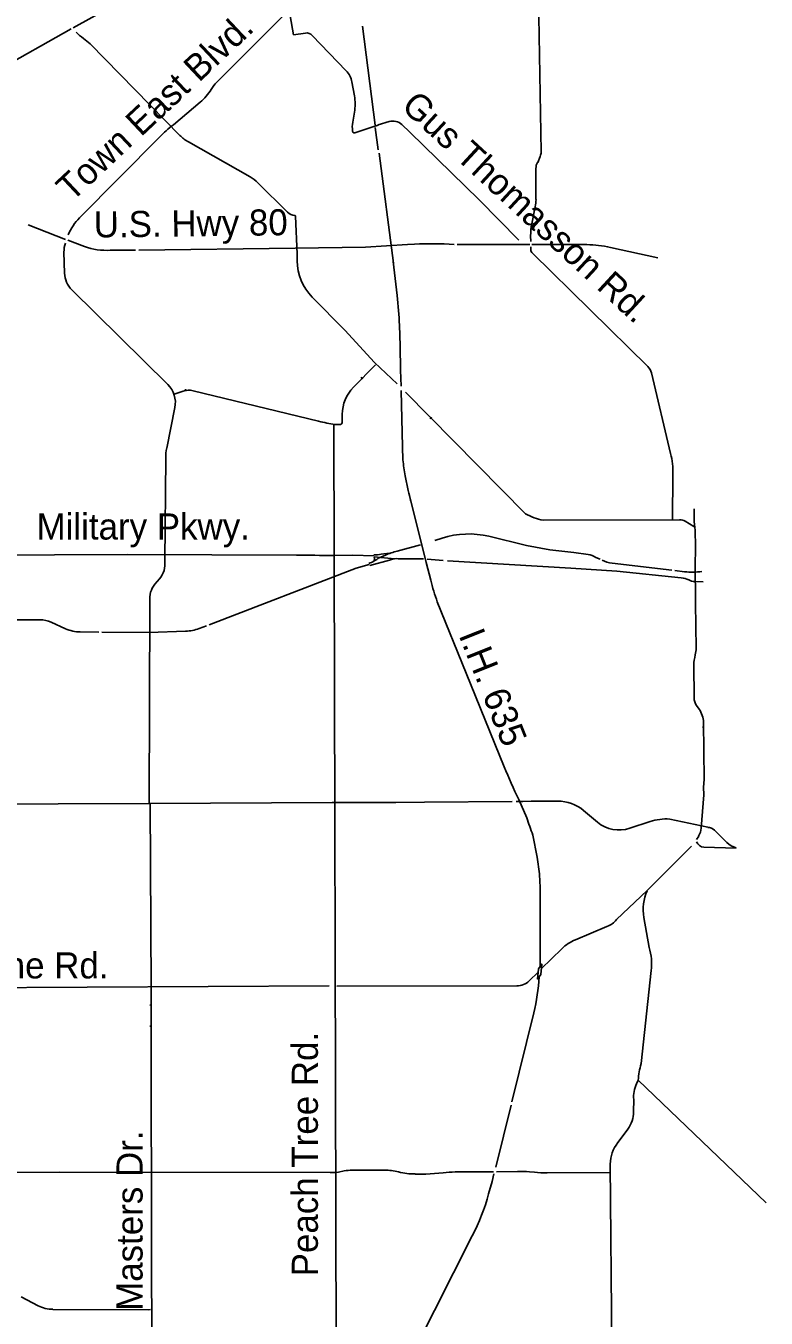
# Model space of a CAD drawing. Extents: x 105094 to 105814, y -291615 to -291123.
# Drawn here: x 105517.8 to 105552.1, y -291508 to -291448 of the extents above; entities that cross this region are included whole.
import ezdxf

# ---------------------------------------------------------------- set-up
doc = ezdxf.new("R2010")
doc.units = 0
doc.layers.add('G_MAP', color=7, linetype='Continuous')

msp = doc.modelspace()

# ---------------------------------------------------------------- linework, layer by layer
at = {"layer": 'G_MAP'}
for p, q in [((105526.465, -291444.508), (105519.999, -291448.096)), ((105530.218, -291448.416), (105529.816, -291446.081)), ((105541.705, -291453.857), (105541.589, -291446.659)), ((105526.657, -291450.614), (105529.889, -291447.382)), ((105519.912, -291448.148), (105513.437, -291451.781)), ((105530.771, -291448.338), (105530.218, -291448.416)), ((105533.418, -291448.019), (105534.006, -291452.608)), ((105532.66, -291450.087), (105531.087, -291448.447)), ((105533.045, -291451.257), (105532.926, -291450.606)), ((105524.65, -291452.595), (105525.896, -291451.545)), ((105532.967, -291452.48), (105533.049, -291452.006)), ((105533.848, -291452.699), (105534.145, -291452.608)), ((105534.145, -291452.605), (105534.654, -291452.449)), ((105520.292, -291456.912), (105524.004, -291453.176)), ((105532.965, -291452.906), (105532.96, -291452.876)), ((105533.848, -291452.699), (105533.067, -291452.969)), ((105534.009, -291452.718), (105534.148, -291453.755)), ((105525.343, -291453.39), (105528.211, -291455.012)), ((105534.19, -291453.906), (105534.858, -291459.023)), ((105541.547, -291454.339), (105541.667, -291454.061)), ((105541.469, -291456.065), (105541.469, -291454.62)), ((105528.566, -291455.281), (105529.948, -291456.653)), ((105541.275, -291457.192), (105541.436, -291456.395)), ((105517.907, -291457.239), (105519.641, -291457.911)), ((105530.319, -291456.842), (105530.386, -291458.595)), ((105519.757, -291457.946), (105520.526, -291458.237)), ((105541.224, -291458.014), (105541.221, -291457.755)), ((105519.602, -291459.472), (105519.572, -291458.503)), ((105521.721, -291458.414), (105522.896, -291458.414)), ((105523.045, -291458.411), (105530.302, -291458.321)), ((105530.302, -291458.321), (105533.554, -291458.266)), ((105530.386, -291458.595), (105530.39, -291458.907)), ((105541.176, -291458.143), (105537.807, -291458.15)), ((105541.227, -291458.374), (105541.224, -291458.256)), ((105546.65, -291463.804), (105541.303, -291458.557)), ((105544.923, -291458.282), (105547.121, -291458.763)), ((105534.849, -291458.941), (105535.028, -291460.518)), ((105524.393, -291464.651), (105519.939, -291460.25)), ((105534.019, -291463.727), (105533.001, -291464.769)), ((105533.363, -291464.312), (105533.428, -291464.396)), ((105547.715, -291467.844), (105546.823, -291464.109)), ((105525.095, -291464.953), (105524.64, -291465.103)), ((105525.209, -291464.86), (105525.231, -291464.954)), ((105531.387, -291466.349), (105525.563, -291464.934)), ((105535.411, -291464.999), (105540.985, -291470.638)), ((105524.338, -291467.591), (105524.717, -291465.715)), ((105532.485, -291466.035), (105532.485, -291466.381)), ((105536.564, -291466.243), (105536.625, -291466.168)), ((105532.097, -291466.509), (105532.215, -291515.51)), ((105532.356, -291466.508), (105532.143, -291466.504)), ((105524.25, -291472.828), (105524.291, -291468.068)), ((105547.809, -291470.951), (105547.822, -291468.807)), ((105535.405, -291468.878), (105535.547, -291469.559)), ((105535.605, -291469.802), (105536.38, -291472.908)), ((105541.809, -291470.942), (105548.131, -291470.918)), ((105548.397, -291470.992), (105548.784, -291471.226)), ((105536.774, -291471.885), (105537.115, -291471.774)), ((105535.033, -291472.379), (105536.105, -291472.085)), ((105532.072, -291472.585), (105532.976, -291472.556)), ((105532.976, -291472.556), (105533.945, -291472.592)), ((105533.131, -291473.16), (105533.729, -291472.992)), ((105533.761, -291473.047), (105534.678, -291472.802)), ((105533.958, -291472.643), (105534.901, -291472.731)), ((105534.194, -291472.679), (105534.481, -291472.563)), ((105534.287, -291472.521), (105534.681, -291472.463)), ((105535.079, -291472.731), (105536.244, -291472.737)), ((105536.38, -291472.908), (105536.587, -291473.722)), ((105536.425, -291472.753), (105537.158, -291472.815)), ((105544.25, -291472.666), (105544.447, -291472.744)), ((105545.005, -291472.932), (105547.764, -291473.257)), ((105533.131, -291473.16), (105526.31, -291475.799)), ((105547.903, -291473.276), (105548.362, -291473.33)), ((105523.785, -291473.909), (105524.004, -291473.667)), ((105548.83, -291473.788), (105549.221, -291473.793)), ((105523.523, -291484.082), (105523.559, -291474.707)), ((105536.89, -291474.726), (105538.224, -291478.033)), ((105518.452, -291475.563), (105513.069, -291475.56)), ((105519.646, -291475.975), (105518.981, -291475.677)), ((105526.181, -291475.844), (105525.836, -291475.969)), ((105521.195, -291476.131), (105520.329, -291476.125)), ((105548.792, -291477.672), (105548.805, -291479.173)), ((105538.224, -291478.033), (105539.996, -291482.379)), ((105548.92, -291479.541), (105549.035, -291479.708)), ((105549.263, -291480.543), (105549.201, -291480.543)), ((105549.208, -291480.769), (105549.263, -291480.769)), ((105549.24, -291480.318), (105549.266, -291482.978)), ((105534.969, -291484.043), (105536.299, -291484.021)), ((105536.299, -291484.021), (105540.362, -291483.995)), ((105540.543, -291483.995), (105540.856, -291483.989)), ((105541.043, -291484.744), (105540.672, -291483.901)), ((105543.673, -291484.407), (105544.322, -291484.949)), ((105545.82, -291485.233), (105546.76, -291484.922)), ((105547.674, -291484.806), (105549.437, -291485.19)), ((105541.521, -291486.572), (105541.324, -291485.549)), ((105548.92, -291485.759), (105549.016, -291485.598)), ((105549.75, -291485.329), (105550.323, -291485.888)), ((105541.657, -291491.646), (105541.668, -291488.627)), ((105543.303, -291490.403), (105544.763, -291489.792)), ((105546.473, -291489.37), (105546.714, -291490.764)), ((105541.715, -291491.762), (105542.673, -291490.821)), ((105541.154, -291492.317), (105541.569, -291491.917)), ((105546.808, -291491.837), (105546.344, -291496.153)), ((105532.223, -291492.557), (105540.584, -291492.547)), ((105523.645, -291493.429), (105523.558, -291493.436)), ((105540.355, -291497.921), (105541.365, -291493.8)), ((105523.558, -291494.421), (105523.645, -291494.417)), ((105546.21, -291496.927), (105546.135, -291497.088)), ((105539.599, -291500.957), (105540.313, -291498.083)), ((105546.003, -291497.811), (105546, -291498.388)), ((105532.568, -291501.133), (105532.31, -291501.187)), ((105534.439, -291501.096), (105532.934, -291501.096)), ((105537.722, -291501.177), (105539.499, -291501.17)), ((105539.644, -291501.167), (105540.613, -291501.157)), ((105541.165, -291501.17), (105541.399, -291501.195)), ((105541.991, -291501.225), (105544.927, -291501.203)), ((105534.008, -291513.065), (105538.513, -291504.143)), ((105517.584, -291506.98), (105518.368, -291507.384)), ((105519.056, -291507.553), (105523.48, -291507.572)), ((105523.483, -291507.572), (105523.583, -291507.565))]:
    msp.add_line(p, q, dxfattribs=at)
for points in [[(105520.474, -291448.587), (105520.791, -291448.845), (105524.946, -291453.086)], [(105535.248, -291452.587), (105535.618, -291452.934), (105538.831, -291456.083), (105540.675, -291457.946)], [(105535.837, -291458.13), (105535.501, -291458.143), (105533.554, -291458.266)], [(105541.282, -291458.15), (105542.635, -291458.146), (105543.823, -291458.157)], [(105531.087, -291460.587), (105532.605, -291462.128), (105533.974, -291463.617), (105535.023, -291464.618)], [(105535.131, -291461.899), (105535.166, -291462.845), (105535.188, -291463.976), (105535.208, -291464.718)], [(105535.217, -291464.925), (105535.282, -291467.535), (105535.295, -291468.138)], [(105548.803, -291470.414), (105548.807, -291470.876)], [(105539.286, -291471.688), (105541.034, -291472.107), (105542.109, -291472.311), (105543.227, -291472.443), (105543.882, -291472.527)], [(105548.862, -291472.017), (105548.862, -291472.363), (105548.856, -291472.915), (105548.862, -291474.794), (105548.894, -291476.887)], [(105512.391, -291472.579), (105522.503, -291472.527), (105530.354, -291472.56)], [(105537.365, -291472.831), (105543.085, -291473.167), (105545.226, -291473.302), (105548.208, -291473.612)], [(105525.215, -291476.09), (105523.523, -291476.151), (105521.324, -291476.135)], [(105549.133, -291485.231), (105549.25, -291483.688), (105549.247, -291483.33), (105549.266, -291482.978)], [(105519.296, -291484.105), (105514.984, -291484.128), (105508.486, -291484.138)], [(105534.969, -291484.043), (105532.017, -291484.043), (105523.559, -291484.079), (105519.296, -291484.105)], [(105523.568, -291484.076), (105523.613, -291492.654), (105523.619, -291498.845), (105523.629, -291501.2), (105523.644, -291512.878)], [(105540.856, -291483.989), (105541.25, -291483.972), (105542.475, -291483.972)], [(105545.203, -291489.466), (105546.624, -291488.113), (105548.681, -291486.065)], [(105549.259, -291486.116), (105550.752, -291486.159)], [(105531.874, -291492.55), (105515.016, -291492.635), (105506.487, -291492.69), (105492.846, -291492.719)], [(105552.147, -291502.617), (105546.21, -291496.927)], [(105545.731, -291499.19), (105545.422, -291499.617), (105545.263, -291499.819)], [(105531.916, -291501.203), (105519.379, -291501.187), (105515.038, -291501.209), (105506.545, -291501.232), (105501.303, -291501.268)], [(105544.911, -291500.815), (105544.985, -291509.351), (105544.957, -291510.894)], [(105535.868, -291501.274), (105536.356, -291501.274), (105537.167, -291501.212)], [(105539.273, -291502.198), (105539.431, -291501.629), (105539.518, -291501.267)]]:
    msp.add_lwpolyline(points, dxfattribs=at)
msp.add_lwpolyline([(105541.578, -291491.754), (105541.539, -291492.232), (105541.696, -291492.016), (105541.735, -291491.538)], close=True, dxfattribs=at)
for centre, radius, start, end in [((105523.895, -291444.211), 5.555, 227.34965, 231.98343), ((105530.822, -291448.701), 0.367, 43.82932, 98.08015), ((105531.931, -291450.787), 1.011, 10.32319, 43.84286), ((105527.726, -291451.681), 1.51, 135.03617, 151.16716), ((105524.346, -291449.705), 2.406, 310.10155, 328.7471), ((105530.94, -291451.643), 2.14, 350.21938, 10.38066), ((105527.303, -291456.192), 4.47, 126.40722, 137.56399), ((105534.267, -291452.701), 1.318, 170.35143, 187.62976), ((105534.832, -291453.029), 0.607, 46.7474, 107.06266), ((105526.22, -291451.838), 1.783, 224.42286, 240.52914), ((105533.041, -291452.896), 0.0774, 186.97324, 289.24024), ((105541.911, -291454.591), 0.443, 145.35516, 183.80648), ((105541.238, -291453.876), 0.467, 336.66831, 2.43907), ((105527.389, -291456.466), 1.67, 45.19952, 60.52826), ((105539.814, -291456.065), 1.656, 348.51587, 0.00435), ((105530.313, -291456.281), 0.521, 225.50225, 265.99529), ((105530.276, -291456.844), 0.0434, 3.06758, 88.22489), ((105521.978, -291458.586), 2.376, 135.20764, 158.13049), ((105543.974, -291457.736), 2.754, 168.60216, 180.39535), ((105520.639, -291458.476), 1.067, 158.32364, 181.46081), ((105521.532, -291455.576), 2.845, 249.28493, 273.80348), ((105536.603, -291479.394), 21.277, 87.13102, 92.06356), ((105541.48, -291458.376), 0.254, 179.72845, 225.52704), ((105543.775, -291463.523), 5.366, 77.63794, 89.48528), ((105532.819, -291458.883), 2.429, 180.56241, 224.53494), ((105520.737, -291459.442), 1.136, 181.53535, 225.3349), ((105517.082, -291462.558), 18.061, 2.09036, 6.48338), ((105546.208, -291464.255), 0.632, 13.35876, 45.54423), ((105523.571, -291465.483), 1.169, 348.5631, 45.34707), ((105525.362, -291465.762), 0.853, 76.33036, 108.25931), ((105534.297, -291466.035), 1.812, 135.65979, 180.00048), ((105533.601, -291457.476), 9.145, 255.98943, 260.82432), ((105532.358, -291466.381), 0.127, 269.00527, 0), ((105526.705, -291468.064), 2.413, 168.68432, 180.10112), ((105542.237, -291467.481), 6.973, 185.41365, 191.55912), ((105543.913, -291468.755), 3.91, 359.23225, 13.46001), ((105529.598, -291471.115), 6.149, 10.00387, 14.65608), ((105542.119, -291468.832), 2.132, 237.889, 261.64094), ((105548.132, -291471.429), 0.511, 58.83031, 90.20674), ((105552.259, -291470.866), 3.452, 180.17123, 188.95349), ((105538.352, -291475.581), 4.003, 76.50486, 108.00496), ((105548.859, -291471.102), 0.145, 238.74031, 257.72294), ((105535.735, -291471.987), 13.127, 359.86913, 2.547), ((105535.577, -291474.93), 2.608, 102.02689, 114.83996), ((105523.17, -291472.968), 1.089, 320.02559, 7.38803), ((105529.886, -291560.846), 88.288, 88.5814, 89.69655), ((105533.045, -291471.204), 1.869, 290.91368, 307.9082), ((105533.896, -291469.953), 2.597, 271.08424, 278.6647), ((105533.799, -291472.739), 0.182, 323.36324, 24.61877), ((105534.99, -291473.394), 0.669, 82.37625, 117.74502), ((105543.585, -291473.873), 1.378, 61.12614, 77.54593), ((105545.173, -291471.463), 1.478, 244.28398, 263.49849), ((105548.1, -291474.634), 1.028, 63.71722, 83.98865), ((105548.732, -291470.13), 3.221, 263.40804, 277.68412), ((105524.631, -291474.58), 1.08, 141.60041, 186.75615), ((105547.115, -291471.088), 10.852, 194.04792, 199.58954), ((105548.838, -291473.222), 0.567, 240.06495, 269.13937), ((105518.452, -291476.855), 1.292, 65.80187, 89.97171), ((105520.342, -291474.425), 1.7, 245.80967, 269.53812), ((105525.142, -291474.055), 2.036, 272.06884, 289.93667), ((105550.731, -291477.693), 1.938, 164.83363, 179.37717), ((105547.791, -291476.913), 1.103, 345.64916, 1.34559), ((105549.455, -291479.171), 0.651, 180.10698, 214.61714), ((105548.08, -291480.367), 1.161, 2.4166, 34.62684), ((105562.541, -291473.279), 24.312, 201.98286, 205.90794), ((105542.475, -291485.842), 1.869, 50.13969, 89.99489), ((105555.884, -291480.012), 15.577, 197.68622, 200.81986), ((105545.327, -291483.745), 1.568, 230.13872, 288.33733), ((105547.527, -291487.307), 2.506, 86.65439, 107.8424), ((105548.292, -291485.166), 0.843, 329.15507, 355.59272), ((105549.39, -291485.72), 0.532, 47.29803, 84.87942), ((105549.269, -291485.753), 0.363, 196.34033, 268.38506), ((105551.099, -291485.092), 1.111, 225.76598, 251.74313), ((105533.944, -291487.987), 7.708, 3.89276, 10.57936), ((105524.43, -291488.547), 17.238, 359.73536, 3.60417), ((105548.599, -291489.003), 2.157, 156.08771, 189.7886), ((105544.435, -291488.892), 0.959, 290.01851, 323.17591), ((105544.074, -291492.248), 2, 112.699, 134.47801), ((105544.453, -291491.502), 2.379, 351.9116, 18.0637), ((105532.277, -291491.57), 9.357, 346.21568, 356.60517), ((105540.583, -291491.724), 0.824, 270.06308, 313.90486), ((105550.085, -291497.202), 3.885, 164.33712, 175.94081), ((105547.281, -291497.672), 1.285, 152.99951, 186.24918), ((105544.586, -291498.36), 1.414, 324.08479, 358.88243), ((105546.565, -291500.839), 1.654, 141.90898, 179.15858), ((105532.063, -291499.982), 1.229, 263.1173, 281.57621), ((105532.934, -291502.914), 1.818, 90.01517, 101.62916), ((105534.434, -291503.828), 2.732, 76.03618, 89.89852), ((105535.87, -291498.115), 3.158, 255.77188, 269.97266), ((105537.787, -291506.552), 5.375, 90.69284, 96.62875), ((105540.792, -291505.304), 4.15, 84.84596, 92.47726), ((105541.952, -291496.034), 5.191, 263.88005, 270.42699), ((105529.524, -291499.506), 10.114, 332.7136, 344.56782), ((105519.063, -291506.036), 1.516, 242.74078, 269.74501)]:
    msp.add_arc(centre, radius, start, end, dxfattribs=at)

# ---------------------------------------------------------------- texts
for s, height, rotation, p in [('Town East Blvd.', 1.21107, 43.22017, (105519.929, -291456.204)), ('Gus Thomasson Rd.', 1.21107, 317.32821, (105535.165, -291451.812)), ('U.S. Hwy 80', 1.21107, 0.68845, (105520.96, -291457.827)), ('I.H. 635', 1.2111, 291.71164, (105537.869, -291476.272)), ('Peach Tree Rd.', 1.21107, 90, (105531.352, -291506.02)), ('Masters Dr.', 1.21107, 90, (105523.218, -291507.623))]:
    msp.add_text(s, height=height, rotation=rotation, dxfattribs=at).set_placement(p)
for s, p in [('Military Pkwy.', (105518.3, -291471.838)), ('Lake June Rd.', (105511.196, -291492.201))]:
    msp.add_text(s, height=1.21107, dxfattribs=at).set_placement(p)

doc.saveas('drawing.dxf')
